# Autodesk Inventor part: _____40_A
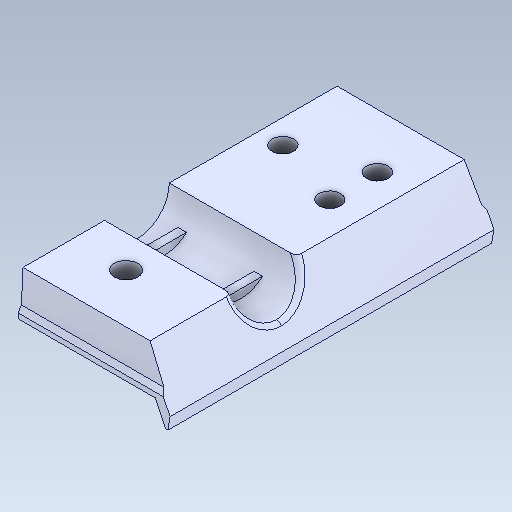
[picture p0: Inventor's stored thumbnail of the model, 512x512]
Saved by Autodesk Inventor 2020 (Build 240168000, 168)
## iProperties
Created: 2017-09
Part Number: _____40_A
Material: Générique
Document SubType Name: Modeling
Designer: bruno
Density: 1 g/cm^3
Appearance: Par défaut
Author: bruno
Sending System: SolidWorks 2016
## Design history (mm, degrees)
feature "Importée1"
node "Solide1"
